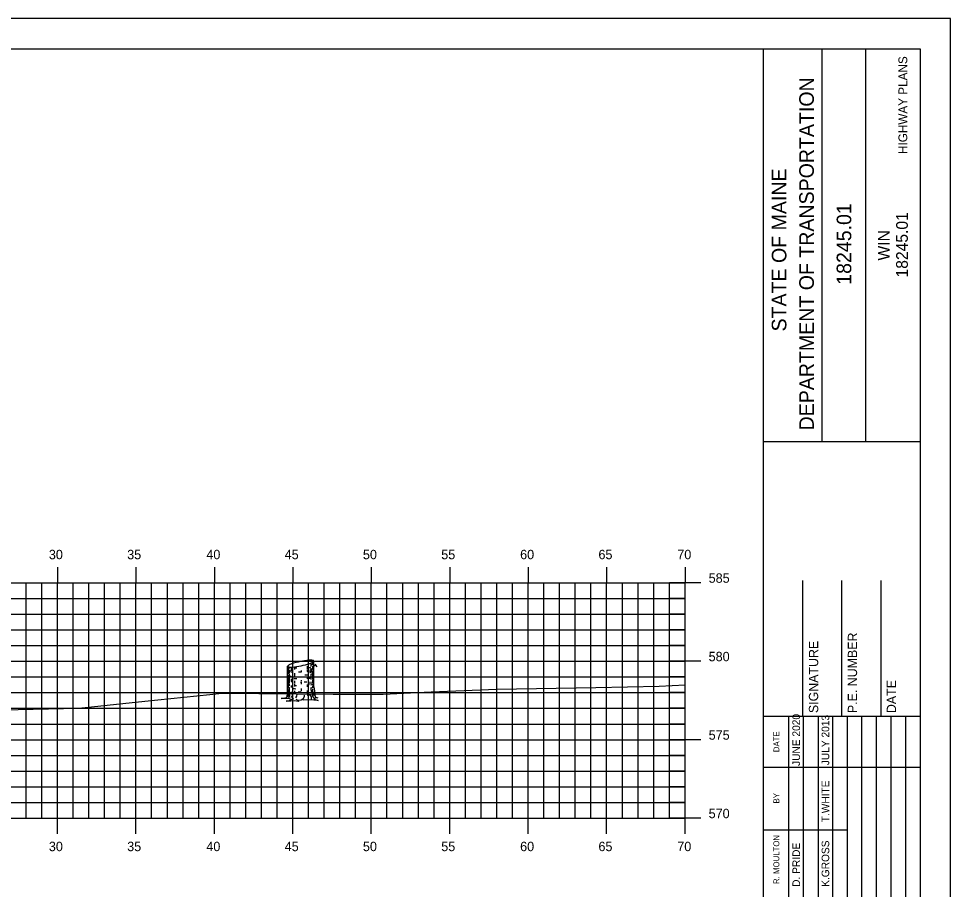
# Model space of a CAD drawing. Extents: x 1048565 to 1048735, y 781387 to 781497.
# Drawn here: x 1048675.4 to 1048734.8, y 781441.8 to 781497.3 of the extents above; entities that cross this region are included whole.
import ezdxf

# ---------------------------------------------------------------- set-up
doc = ezdxf.new("R2010")
doc.units = 0
for name, color, linetype in [('BORDER', 7, 'Continuous'), ('H_V ANNOTATION', 7, 'Continuous'), ('HIGHWAY_TITLE', 7, 'Continuous'), ('M_Trees_Conifer_Pay', 7, 'Continuous'), ('MAJOR', 7, 'Continuous'), ('MINOR', 7, 'Continuous'), ('PLOT BOUNDARY', 7, 'Continuous'), ('S_Roadway_Centerline', 7, 'Continuous')]:
    doc.layers.add(name, color=color, linetype=linetype)

msp = doc.modelspace()

# ---------------------------------------------------------------- linework, layer by layer
at = {"layer": 'BORDER'}
for p, q in [((1048722.876, 781390.375), (1048722.876, 781495.375)), ((1048726.605, 781470.373), (1048726.605, 781495.373)), ((1048729.4, 781470.373), (1048729.4, 781495.373)), ((1048722.877, 781470.37), (1048732.876, 781470.37)), ((1048725.376, 781452.878), (1048725.376, 781461.526)), ((1048727.876, 781452.878), (1048727.876, 781461.526)), ((1048730.376, 781452.878), (1048730.376, 781461.526)), ((1048722.876, 781452.878), (1048732.876, 781452.878))]:
    msp.add_line(p, q, dxfattribs=at)
msp.add_lwpolyline([(1048572.876, 781390.375), (1048732.876, 781390.375), (1048732.876, 781495.375), (1048572.876, 781495.375)], close=True, dxfattribs=at)
for points in [[(1048724.491, 781449.628), (1048724.491, 781452.878)], [(1048725.424, 781435.381), (1048725.424, 781452.878)], [(1048726.355, 781452.878), (1048726.355, 781435.381)], [(1048727.287, 781435.381), (1048727.287, 781452.878)], [(1048728.219, 781435.381), (1048728.219, 781452.878)], [(1048729.15, 781435.381), (1048729.15, 781452.878)], [(1048730.082, 781435.381), (1048730.082, 781452.878)], [(1048731.014, 781435.381), (1048731.014, 781452.878)], [(1048731.945, 781435.381), (1048731.945, 781452.878)], [(1048724.492, 781435.381), (1048724.492, 781452.172)], [(1048722.876, 781449.628), (1048732.876, 781449.628)], [(1048722.876, 781445.628), (1048724.492, 781445.628)], [(1048724.491, 781445.628), (1048728.218, 781445.628)]]:
    msp.add_lwpolyline(points, dxfattribs=at)
at = {"layer": 'M_Trees_Conifer_Pay'}
for p, q in [((1048694.015, 781456.254), (1048694.015, 781456.031)), ((1048694.132, 781456.315), (1048694.132, 781456.153)), ((1048694.204, 781454.741), (1048694.204, 781456.388)), ((1048692.54, 781454.33), (1048692.54, 781456.052)), ((1048692.587, 781456.015), (1048692.587, 781455.544)), ((1048692.645, 781456.004), (1048692.645, 781455.906)), ((1048692.645, 781455.832), (1048692.645, 781455.628)), ((1048692.771, 781455.996), (1048692.771, 781455.764)), ((1048692.771, 781455.723), (1048692.771, 781455.649)), ((1048692.991, 781456.016), (1048692.991, 781455.848)), ((1048692.991, 781455.611), (1048692.991, 781455.374)), ((1048693.396, 781455.785), (1048693.396, 781455.689)), ((1048693.787, 781456.058), (1048693.787, 781455.859)), ((1048693.787, 781455.801), (1048693.787, 781455.712)), ((1048694.015, 781455.943), (1048694.015, 781455.895)), ((1048694.072, 781455.76), (1048694.021, 781455.7)), ((1048694.132, 781456.085), (1048694.132, 781455.957)), ((1048694.132, 781455.77), (1048694.132, 781455.434)), ((1048692.587, 781455.479), (1048692.587, 781455.171)), ((1048692.587, 781455.124), (1048692.587, 781454.632)), ((1048692.645, 781455.57), (1048692.645, 781455.371)), ((1048692.645, 781455.323), (1048692.645, 781454.987)), ((1048692.771, 781455.245), (1048692.771, 781455.107)), ((1048692.991, 781455.13), (1048692.991, 781454.977)), ((1048693.396, 781455.171), (1048693.396, 781455.097)), ((1048693.396, 781455.072), (1048693.396, 781454.924)), ((1048693.787, 781455.365), (1048693.787, 781455.26)), ((1048694.015, 781455.56), (1048694.015, 781455.428)), ((1048694.015, 781455.317), (1048694.015, 781455.208)), ((1048694.015, 781455.072), (1048694.015, 781454.93)), ((1048694.132, 781455.397), (1048694.132, 781455.235)), ((1048694.132, 781455.187), (1048694.132, 781454.971)), ((1048692.587, 781454.578), (1048692.587, 781454.33)), ((1048692.645, 781454.934), (1048692.645, 781454.798)), ((1048692.645, 781454.699), (1048692.645, 781454.321)), ((1048692.771, 781454.835), (1048692.771, 781454.693)), ((1048692.771, 781454.432), (1048692.771, 781454.337)), ((1048692.991, 781454.934), (1048692.991, 781454.761)), ((1048692.991, 781454.483), (1048692.991, 781454.33)), ((1048693.396, 781454.632), (1048693.396, 781454.479)), ((1048693.787, 781454.893), (1048693.787, 781454.746)), ((1048693.787, 781454.514), (1048693.787, 781454.426)), ((1048694.015, 781454.703), (1048694.015, 781454.531)), ((1048694.132, 781454.94), (1048694.132, 781454.866)), ((1048694.132, 781454.825), (1048694.132, 781454.652)), ((1048692.771, 781453.937), (1048692.934, 781454.001)), ((1048693.208, 781453.873), (1048693.082, 781453.937))]:
    msp.add_line(p, q, dxfattribs=at)
for points in [[(1048694.021, 781455.886), (1048694.058, 781455.811), (1048694.105, 781455.869), (1048694.163, 781455.937), (1048694.255, 781456.13), (1048694.319, 781456.178), (1048694.35, 781456.184)], [(1048693.987, 781455.848), (1048693.957, 781455.764), (1048693.953, 781455.696), (1048693.983, 781455.632)], [(1048694.035, 781455.632), (1048694.072, 781455.76), (1048694.136, 781455.875), (1048694.166, 781455.943), (1048694.235, 781456.089)], [(1048694.25, 781456.119), (1048694.325, 781456.126), (1048694.397, 781456.027)], [(1048692.719, 781455.358), (1048692.713, 781455.453), (1048692.756, 781455.43), (1048692.756, 781455.336)], [(1048693.858, 781454.959), (1048693.871, 781454.882), (1048693.918, 781454.893), (1048693.905, 781455.059)], [(1048694.204, 781454.741), (1048694.255, 781454.479), (1048694.271, 781454.205), (1048694.329, 781454.08), (1048694.465, 781454.049), (1048694.235, 781454.012), (1048694.235, 781454.012), (1048694.241, 781453.964), (1048694.488, 781453.87), (1048694.214, 781453.886), (1048693.858, 781453.907), (1048693.537, 781453.896), (1048693.543, 781453.979), (1048693.395, 781453.896), (1048693.208, 781453.873), (1048693.232, 781453.806), (1048692.964, 781453.849), (1048692.744, 781453.822), (1048692.451, 781453.839), (1048692.74, 781453.896), (1048692.771, 781453.937), (1048692.608, 781453.995), (1048692.371, 781454.006), (1048692.13, 781454.006), (1048692.472, 781454.063), (1048692.514, 781454.143), (1048692.54, 781454.33)], [(1048694.031, 781454.453), (1048694.105, 781454.348), (1048694.109, 781454.174), (1048694.235, 781454.012)], [(1048694.13, 781454.598), (1048694.136, 781454.453), (1048694.183, 781454.384), (1048694.193, 781454.185)], [(1048692.588, 781454.283), (1048692.567, 781454.205), (1048692.546, 781454.111)], [(1048692.666, 781454.263), (1048692.672, 781454.147), (1048692.619, 781454.059), (1048692.608, 781453.995)], [(1048692.829, 781454.29), (1048692.829, 781454.158), (1048692.74, 781454.059)], [(1048693.055, 781454.049), (1048693.123, 781454.143), (1048693.149, 781454.283)], [(1048693.543, 781453.979), (1048693.617, 781454.121), (1048693.627, 781454.222)], [(1048693.794, 781454.348), (1048693.804, 781454.222), (1048693.878, 781454.178)], [(1048694.072, 781453.958), (1048694.058, 781454.096), (1048693.983, 781454.225)]]:
    msp.add_lwpolyline(points, dxfattribs=at)
for centre, radius, start, end in [((1048693.039, 781455.446), 0.802, 108.05939, 124.2194), ((1048694.396, 781451.285), 5.179, 101.7194, 108.05939), ((1048694.396, 781451.285), 5.179, 95.37941, 101.7194), ((1048692.348, 781461.155), 5.179, 281.7194, 288.05939), ((1048693.985, 781455.643), 0.802, 79.2194, 95.37941), ((1048693.705, 781456.993), 0.802, 288.05939, 304.2194), ((1048693.873, 781456.701), 0.571, 284.43166, 292.41325), ((1048694.088, 781456.184), 0.251, 71.05013, 79.2194), ((1048694.015, 781456.538), 0.251, 304.2194, 312.38868), ((1048694.072, 781456.356), 0.172, 300, 311.25059), ((1048694.143, 781456.344), 0.0817, 56.7194, 71.05013), ((1048694.129, 781456.413), 0.0817, 312.38868, 326.7194), ((1048694.145, 781456.273), 0.0624, 311.25059, 330), ((1048694.159, 781456.368), 0.0527, 46.92298, 56.7194), ((1048694.174, 781456.383), 0.0314, 34.2194, 46.92298), ((1048694.153, 781456.397), 0.0527, 326.7194, 336.51582), ((1048694.16, 781456.264), 0.0441, 330, 343.94846), ((1048694.178, 781456.386), 0.0264, 23.40735, 34.2194), ((1048694.173, 781456.389), 0.0314, 336.51582, 349.2194), ((1048694.181, 781456.388), 0.0226, 11.7194, 23.40735), ((1048694.181, 781456.388), 0.0226, 0.03145, 11.7194), ((1048694.178, 781456.388), 0.0264, 349.2194, 0.03145), ((1048694.171, 781456.261), 0.0334, 343.94846, 354.21506), ((1048692.572, 781455.874), 0.0334, 163.94846, 180), ((1048692.572, 781455.874), 0.0334, 180, 196.05154), ((1048692.571, 781456.051), 0.0314, 156.51582, 169.2194), ((1048692.566, 781456.052), 0.0264, 169.2194, 180.03145), ((1048692.563, 781456.052), 0.0226, 180.03145, 191.7194), ((1048692.563, 781456.052), 0.0226, 191.7194, 203.40735), ((1048692.582, 781455.877), 0.0441, 196.05154, 210), ((1048692.591, 781456.043), 0.0527, 146.7194, 156.51582), ((1048692.566, 781456.053), 0.0264, 203.40735, 214.2194), ((1048692.57, 781456.056), 0.0314, 214.2194, 226.92298), ((1048692.598, 781455.886), 0.0624, 210, 228.74941), ((1048692.615, 781456.027), 0.0817, 132.38868, 146.7194), ((1048692.585, 781456.072), 0.0527, 226.92298, 236.7194), ((1048692.601, 781456.096), 0.0817, 236.7194, 251.05013), ((1048692.671, 781455.969), 0.172, 228.74941, 240), ((1048692.729, 781455.902), 0.251, 124.2194, 132.38868), ((1048692.656, 781456.256), 0.251, 251.05013, 259.2194), ((1048692.87, 781456.314), 0.571, 240, 240.33672), ((1048692.871, 781456.103), 0.571, 240, 247.05866), ((1048692.759, 781456.797), 0.802, 259.2194, 275.37941), ((1048692.87, 781456.314), 0.571, 246.85973, 257.98457), ((1048692.348, 781461.155), 5.179, 275.37941, 281.7194), ((1048693.372, 781460.064), 4.124, 264.6955, 266.73309), ((1048693.371, 781459.831), 4.124, 268.07512, 270), ((1048693.371, 781459.831), 4.124, 270, 270.35814), ((1048693.371, 781459.831), 4.124, 275.78493, 277.05584), ((1048693.372, 781460.064), 4.124, 276.23804, 278.1032), ((1048693.873, 781456.547), 0.571, 278.1032, 284.36665), ((1048693.873, 781456.103), 0.571, 284.44928, 297.04285), ((1048693.873, 781456.547), 0.571, 297.0237, 300), ((1048694.072, 781456.202), 0.172, 300, 311.25059), ((1048694.145, 781456.119), 0.0624, 311.25059, 330), ((1048694.16, 781456.11), 0.0441, 330, 343.94846), ((1048694.171, 781456.107), 0.0334, 343.94846, 354.21506), ((1048694.171, 781455.663), 0.0334, 343.94846, 354.21506), ((1048692.572, 781455.427), 0.0334, 163.94846, 180), ((1048692.572, 781455.427), 0.0334, 180, 196.05154), ((1048692.572, 781455.217), 0.0334, 163.94846, 180), ((1048692.572, 781455.217), 0.0334, 180, 196.05154), ((1048692.572, 781454.98), 0.0334, 163.94846, 180), ((1048692.582, 781455.43), 0.0441, 196.05154, 210), ((1048692.582, 781455.22), 0.0441, 196.05154, 210), ((1048692.598, 781455.439), 0.0624, 210, 228.74941), ((1048692.598, 781455.229), 0.0624, 210, 228.74941), ((1048692.671, 781455.522), 0.172, 228.74941, 240), ((1048692.671, 781455.312), 0.172, 228.74941, 240), ((1048692.87, 781455.867), 0.571, 240, 240.33672), ((1048692.87, 781455.657), 0.571, 240, 246.85973), ((1048692.87, 781455.657), 0.571, 259.27072, 261.8968), ((1048693.371, 781459.175), 4.124, 261.8968, 263.14738), ((1048693.371, 781459.385), 4.124, 264.08098, 266.66759), ((1048693.371, 781459.175), 4.124, 270, 270.35814), ((1048693.371, 781459.175), 4.124, 273.14934, 275.45691), ((1048693.372, 781459.62), 4.124, 273.70524, 275.95043), ((1048693.371, 781459.385), 4.124, 277.61247, 278.1032), ((1048693.871, 781455.867), 0.571, 278.1032, 286.92962), ((1048693.871, 781455.867), 0.571, 297.18959, 300), ((1048693.871, 781455.657), 0.571, 297.18959, 300), ((1048694.071, 781455.522), 0.172, 300, 311.25059), ((1048694.071, 781455.312), 0.172, 300, 311.25059), ((1048694.143, 781455.439), 0.0624, 311.25059, 330), ((1048694.143, 781455.229), 0.0624, 311.25059, 330), ((1048694.159, 781455.43), 0.0441, 330, 343.94846), ((1048694.159, 781455.22), 0.0441, 330, 343.94846), ((1048694.169, 781455.427), 0.0334, 343.94846, 354.21506), ((1048694.169, 781455.217), 0.0334, 343.94846, 354.21506), ((1048692.572, 781454.98), 0.0334, 180, 196.05154), ((1048692.572, 781454.783), 0.0334, 163.94846, 180), ((1048692.572, 781454.587), 0.0334, 163.94846, 180), ((1048692.572, 781454.587), 0.0334, 180, 196.05154), ((1048692.582, 781454.983), 0.0441, 196.05154, 210), ((1048692.582, 781454.59), 0.0441, 196.05154, 210), ((1048692.598, 781454.993), 0.0624, 210, 228.74941), ((1048692.598, 781454.599), 0.0624, 210, 228.74941), ((1048692.671, 781455.075), 0.172, 228.74941, 240), ((1048692.671, 781454.682), 0.172, 228.74941, 240), ((1048692.87, 781455.42), 0.571, 240, 246.85973), ((1048692.859, 781455.229), 0.571, 241.23686, 248.02677), ((1048692.87, 781455.027), 0.571, 240, 246.85973), ((1048693.371, 781458.74), 4.124, 263.49906, 265.83975), ((1048693.371, 781458.938), 4.124, 264.71603, 266.31934), ((1048693.371, 781458.544), 4.124, 267.81166, 270), ((1048693.371, 781458.544), 4.124, 270, 270.13279), ((1048693.371, 781458.544), 4.124, 275.78493, 276.78961), ((1048693.871, 781455.42), 0.571, 285.39827, 297.18959), ((1048693.871, 781455.027), 0.571, 288.50673, 297.27208), ((1048693.871, 781455.223), 0.571, 289.29072, 300), ((1048694.071, 781454.877), 0.172, 300, 311.25059), ((1048694.143, 781454.795), 0.0624, 311.25059, 330), ((1048694.159, 781454.786), 0.0441, 330, 343.94846), ((1048694.169, 781454.783), 0.0334, 343.94846, 354.21506), ((1048692.572, 781454.367), 0.0334, 163.94846, 180), ((1048692.572, 781454.367), 0.0334, 180, 196.05154), ((1048692.582, 781454.37), 0.0441, 196.05154, 210), ((1048692.598, 781454.379), 0.0624, 210, 228.74941), ((1048692.671, 781454.462), 0.172, 228.74941, 240), ((1048692.87, 781454.807), 0.571, 240, 244.53138), ((1048693.371, 781458.324), 4.124, 262.44379, 263.51202), ((1048693.371, 781458.324), 4.124, 277.36842, 278.1032), ((1048693.871, 781454.807), 0.571, 278.1032, 281.63703), ((1048694.071, 781454.462), 0.172, 300, 311.25059), ((1048694.143, 781454.379), 0.0624, 311.25059, 330), ((1048694.159, 781454.37), 0.0441, 330, 343.94846), ((1048694.169, 781454.367), 0.0334, 343.94846, 354.21506)]:
    msp.add_arc(centre, radius, start, end, dxfattribs=at)
at = {"layer": 'MAJOR'}
for p, q in [((1048677.876, 781462.377), (1048677.876, 781461.375)), ((1048682.876, 781462.377), (1048682.876, 781461.375)), ((1048687.876, 781462.377), (1048687.876, 781461.375)), ((1048692.876, 781462.377), (1048692.876, 781461.375)), ((1048697.876, 781462.377), (1048697.876, 781461.375)), ((1048702.876, 781462.377), (1048702.876, 781461.375)), ((1048707.876, 781462.377), (1048707.876, 781461.375)), ((1048712.876, 781462.377), (1048712.876, 781461.375)), ((1048717.876, 781462.377), (1048717.876, 781461.375)), ((1048577.876, 781461.375), (1048717.876, 781461.375)), ((1048577.876, 781461.375), (1048717.876, 781461.375)), ((1048677.876, 781446.375), (1048677.876, 781461.375)), ((1048682.876, 781446.375), (1048682.876, 781461.375)), ((1048687.876, 781446.375), (1048687.876, 781461.375)), ((1048692.876, 781446.375), (1048692.876, 781461.375)), ((1048697.876, 781446.375), (1048697.876, 781461.375)), ((1048702.876, 781446.375), (1048702.876, 781461.375)), ((1048707.876, 781446.375), (1048707.876, 781461.375)), ((1048712.876, 781446.375), (1048712.876, 781461.375)), ((1048718.878, 781461.375), (1048716.874, 781461.375)), ((1048717.876, 781446.375), (1048717.876, 781461.375)), ((1048717.876, 781446.375), (1048717.876, 781461.375)), ((1048577.876, 781456.375), (1048717.876, 781456.375)), ((1048718.878, 781456.375), (1048716.874, 781456.375)), ((1048577.876, 781451.375), (1048717.876, 781451.375)), ((1048718.878, 781451.375), (1048716.874, 781451.375)), ((1048577.876, 781446.375), (1048717.876, 781446.375)), ((1048577.876, 781446.375), (1048717.876, 781446.375)), ((1048677.876, 781445.373), (1048677.876, 781446.375)), ((1048682.876, 781445.373), (1048682.876, 781446.375)), ((1048687.876, 781445.373), (1048687.876, 781446.375)), ((1048692.876, 781445.373), (1048692.876, 781446.375)), ((1048697.876, 781445.373), (1048697.876, 781446.375)), ((1048702.876, 781445.373), (1048702.876, 781446.375)), ((1048707.876, 781445.373), (1048707.876, 781446.375)), ((1048712.876, 781445.373), (1048712.876, 781446.375)), ((1048718.878, 781446.375), (1048716.874, 781446.375)), ((1048717.876, 781445.373), (1048717.876, 781446.375))]:
    msp.add_line(p, q, dxfattribs=at)
at = {"layer": 'MINOR'}
for p, q in [((1048675.876, 781446.375), (1048675.876, 781461.375)), ((1048676.876, 781446.375), (1048676.876, 781461.375)), ((1048678.876, 781446.375), (1048678.876, 781461.375)), ((1048679.876, 781446.375), (1048679.876, 781461.375)), ((1048680.876, 781446.375), (1048680.876, 781461.375)), ((1048681.876, 781446.375), (1048681.876, 781461.375)), ((1048683.876, 781446.375), (1048683.876, 781461.375)), ((1048684.876, 781446.375), (1048684.876, 781461.375)), ((1048685.876, 781446.375), (1048685.876, 781461.375)), ((1048686.876, 781446.375), (1048686.876, 781461.375)), ((1048688.876, 781446.375), (1048688.876, 781461.375)), ((1048689.876, 781446.375), (1048689.876, 781461.375)), ((1048690.876, 781446.375), (1048690.876, 781461.375)), ((1048691.876, 781446.375), (1048691.876, 781461.375)), ((1048693.876, 781446.375), (1048693.876, 781461.375)), ((1048694.876, 781446.375), (1048694.876, 781461.375)), ((1048695.876, 781446.375), (1048695.876, 781461.375)), ((1048696.876, 781446.375), (1048696.876, 781461.375)), ((1048698.876, 781446.375), (1048698.876, 781461.375)), ((1048699.876, 781446.375), (1048699.876, 781461.375)), ((1048700.876, 781446.375), (1048700.876, 781461.375)), ((1048701.876, 781446.375), (1048701.876, 781461.375)), ((1048703.876, 781446.375), (1048703.876, 781461.375)), ((1048704.876, 781446.375), (1048704.876, 781461.375)), ((1048705.876, 781446.375), (1048705.876, 781461.375)), ((1048706.876, 781446.375), (1048706.876, 781461.375)), ((1048708.876, 781446.375), (1048708.876, 781461.375)), ((1048709.876, 781446.375), (1048709.876, 781461.375)), ((1048710.876, 781446.375), (1048710.876, 781461.375)), ((1048711.876, 781446.375), (1048711.876, 781461.375)), ((1048713.876, 781446.375), (1048713.876, 781461.375)), ((1048714.876, 781446.375), (1048714.876, 781461.375)), ((1048715.876, 781446.375), (1048715.876, 781461.375)), ((1048716.876, 781446.375), (1048716.876, 781461.375)), ((1048577.876, 781460.375), (1048717.876, 781460.375)), ((1048717.876, 781460.375), (1048716.874, 781460.375)), ((1048577.876, 781459.375), (1048717.876, 781459.375)), ((1048717.876, 781459.375), (1048716.874, 781459.375)), ((1048577.876, 781458.375), (1048717.876, 781458.375)), ((1048717.876, 781458.375), (1048716.874, 781458.375)), ((1048577.876, 781457.375), (1048717.876, 781457.375)), ((1048717.876, 781457.375), (1048716.874, 781457.375)), ((1048577.876, 781455.375), (1048717.876, 781455.375)), ((1048717.876, 781455.375), (1048716.874, 781455.375)), ((1048577.876, 781454.375), (1048717.876, 781454.375)), ((1048717.876, 781454.375), (1048716.874, 781454.375)), ((1048577.876, 781453.375), (1048717.876, 781453.375)), ((1048717.876, 781453.375), (1048716.874, 781453.375)), ((1048577.876, 781452.375), (1048717.876, 781452.375)), ((1048717.876, 781452.375), (1048716.874, 781452.375)), ((1048577.876, 781450.375), (1048717.876, 781450.375)), ((1048717.876, 781450.375), (1048716.874, 781450.375)), ((1048577.876, 781449.375), (1048717.876, 781449.375)), ((1048717.876, 781449.375), (1048716.874, 781449.375)), ((1048577.876, 781448.375), (1048717.876, 781448.375)), ((1048717.876, 781448.375), (1048716.874, 781448.375)), ((1048577.876, 781447.375), (1048717.876, 781447.375)), ((1048717.876, 781447.375), (1048716.874, 781447.375))]:
    msp.add_line(p, q, dxfattribs=at)
at = {"layer": 'PLOT BOUNDARY'}
msp.add_lwpolyline([(1048564.783, 781387.316), (1048734.783, 781387.316), (1048734.783, 781497.316), (1048564.783, 781497.316)], close=True, dxfattribs=at)
at = {"layer": 'S_Roadway_Centerline'}
msp.add_lwpolyline([(1048672.434, 781453.234), (1048679.244, 781453.391), (1048683.452, 781453.833), (1048687.587, 781454.249), (1048688.345, 781454.345), (1048695.445, 781454.282), (1048698.626, 781454.288), (1048701.698, 781454.424), (1048705.875, 781454.588), (1048712.189, 781454.692), (1048716.229, 781454.78), (1048717.876, 781454.868)], dxfattribs=at)

# ---------------------------------------------------------------- texts
at = {"layer": 'BORDER'}
for s, height, p in [('DEPARTMENT OF TRANSPORTATION', 0.93176, (1048726.083, 781471.081)), ('STATE OF MAINE', 0.93176, (1048724.331, 781477.387)), ('18245.01', 0.9318, (1048728.468, 781480.36)), ('18245.01', 0.7453, (1048732.072, 781480.826)), ('WIN', 0.7453, (1048730.913, 781481.905)), ('P.E. NUMBER', 0.59055, (1048728.837, 781453.071)), ('SIGNATURE', 0.5906, (1048726.357, 781453.071)), ('DATE', 0.5906, (1048731.317, 781453.071)), ('JUNE 2020', 0.4845, (1048725.199, 781449.704)), ('JULY 2013', 0.4845, (1048727.062, 781449.75)), ('DATE', 0.3714, (1048723.88, 781450.584)), ('T.WHITE', 0.4845, (1048727.062, 781446.114)), ('BY', 0.3714, (1048723.88, 781447.313)), ('R. MOULTON', 0.3727, (1048723.88, 781442.181)), ('K.GROSS', 0.4845, (1048727.062, 781442.002)), ('D. PRIDE', 0.4845, (1048725.199, 781442.002))]:
    msp.add_text(s, height=height, rotation=90, dxfattribs=at).set_placement(p)
at = {"layer": 'H_V ANNOTATION'}
for s, p in [('30', (1048677.325, 781462.875)), ('35', (1048682.317, 781462.875)), ('40', (1048687.362, 781462.875)), ('45', (1048692.354, 781462.875)), ('50', (1048697.341, 781462.875)), ('55', (1048702.333, 781462.875)), ('60', (1048707.362, 781462.875)), ('65', (1048712.354, 781462.875)), ('70', (1048717.378, 781462.875)), ('585', (1048719.376, 781461.375)), ('580', (1048719.376, 781456.375)), ('575', (1048719.376, 781451.375)), ('570', (1048719.376, 781446.375)), ('30', (1048677.325, 781444.275)), ('35', (1048682.317, 781444.275)), ('40', (1048687.362, 781444.275)), ('45', (1048692.354, 781444.275)), ('50', (1048697.341, 781444.275)), ('55', (1048702.333, 781444.275)), ('60', (1048707.362, 781444.275)), ('65', (1048712.354, 781444.275)), ('70', (1048717.378, 781444.275))]:
    msp.add_text(s, height=0.6, dxfattribs=at).set_placement(p)
at = {"layer": 'HIGHWAY_TITLE'}
msp.add_text('HIGHWAY PLANS', height=0.55901, rotation=90, dxfattribs=at).set_placement((1048732.034, 781488.691))

doc.saveas('drawing.dxf')
